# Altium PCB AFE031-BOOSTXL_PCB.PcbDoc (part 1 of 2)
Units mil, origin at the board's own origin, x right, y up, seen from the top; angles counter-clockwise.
Board outline 2300 x 2000 mil, 4 copper layers (Top Layer, POWER, GND, Bottom Layer), stack 61.6 mil thick; 92 components, 52 nets, 268 pads, 81 vias.
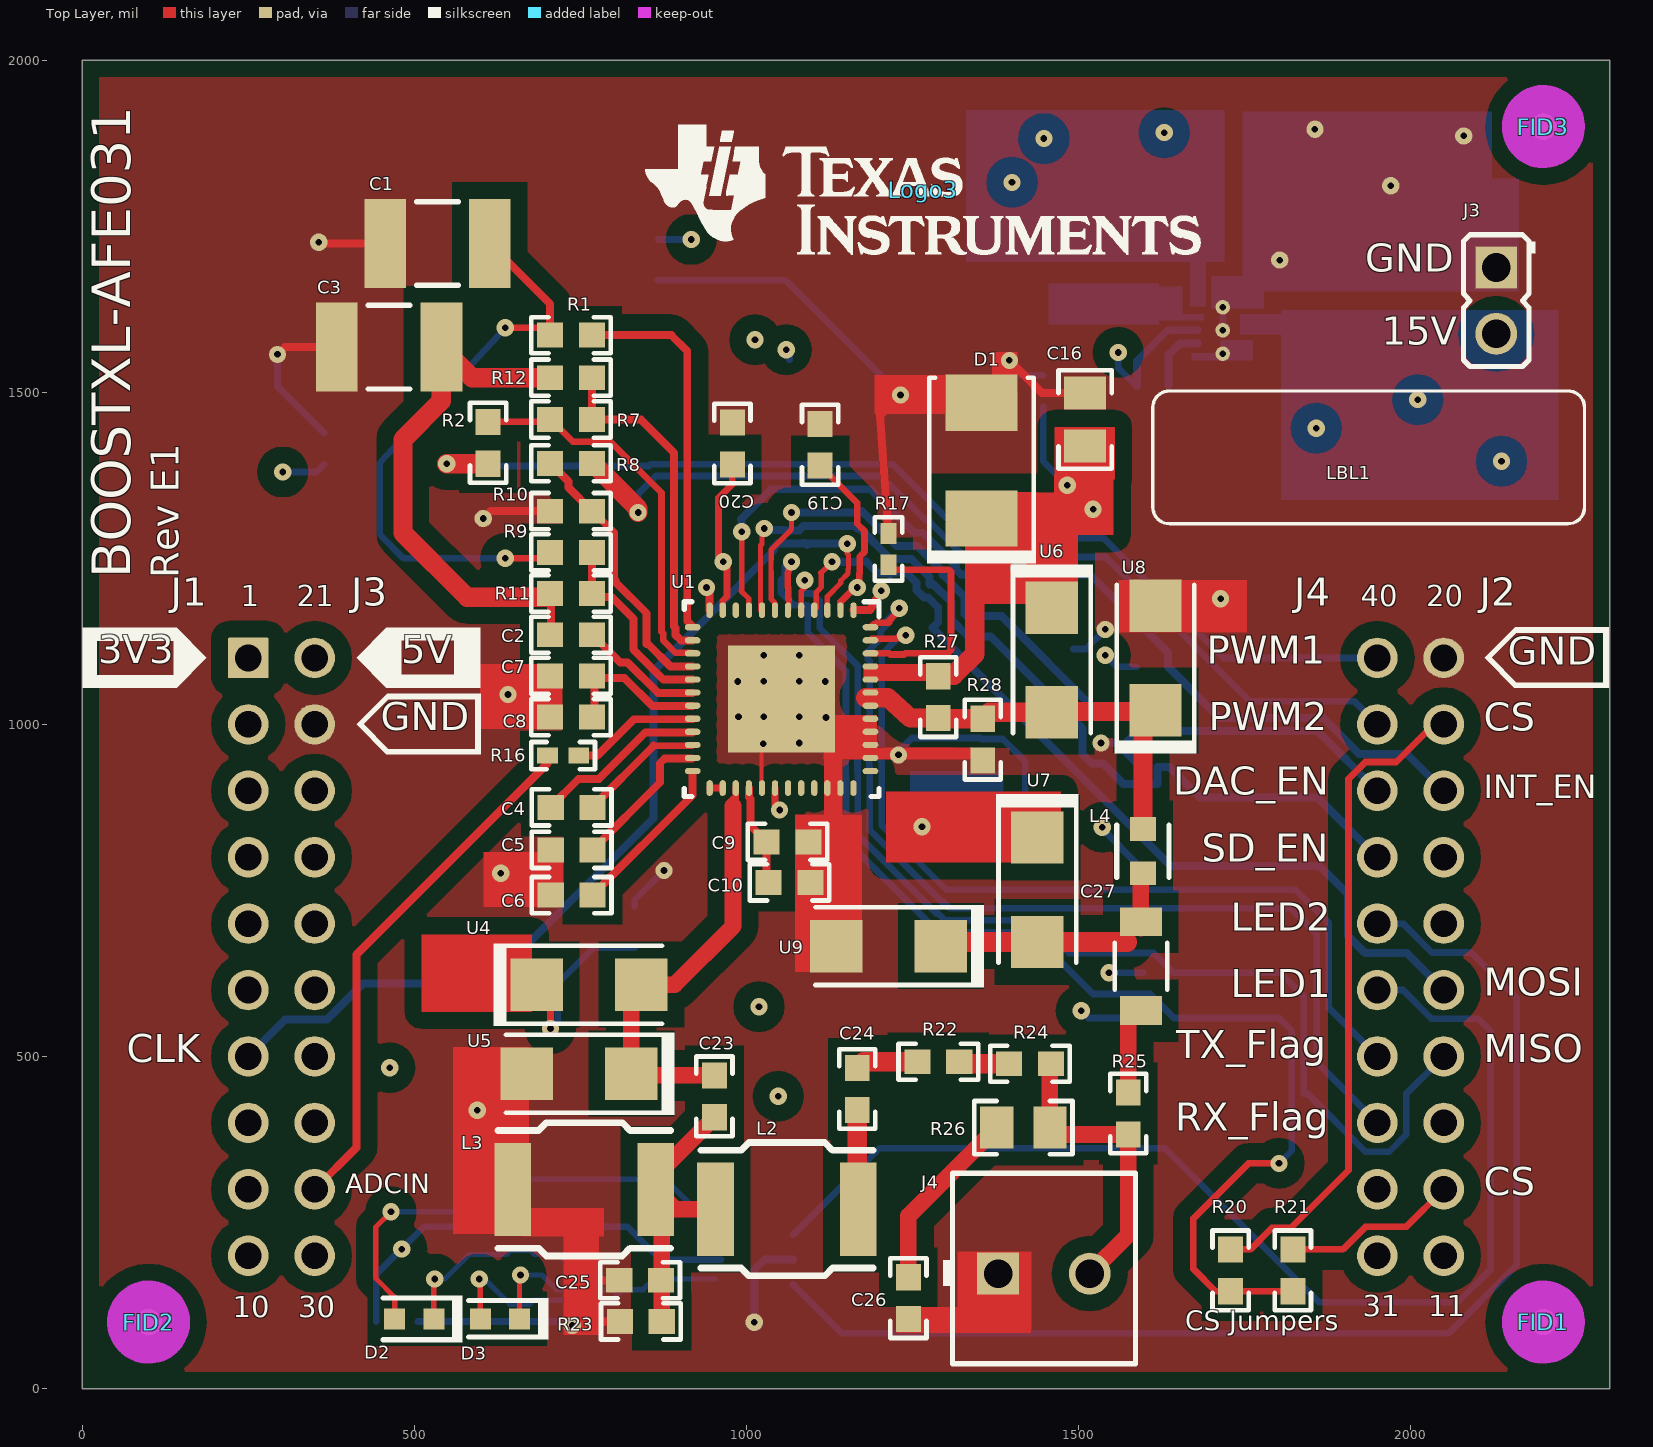
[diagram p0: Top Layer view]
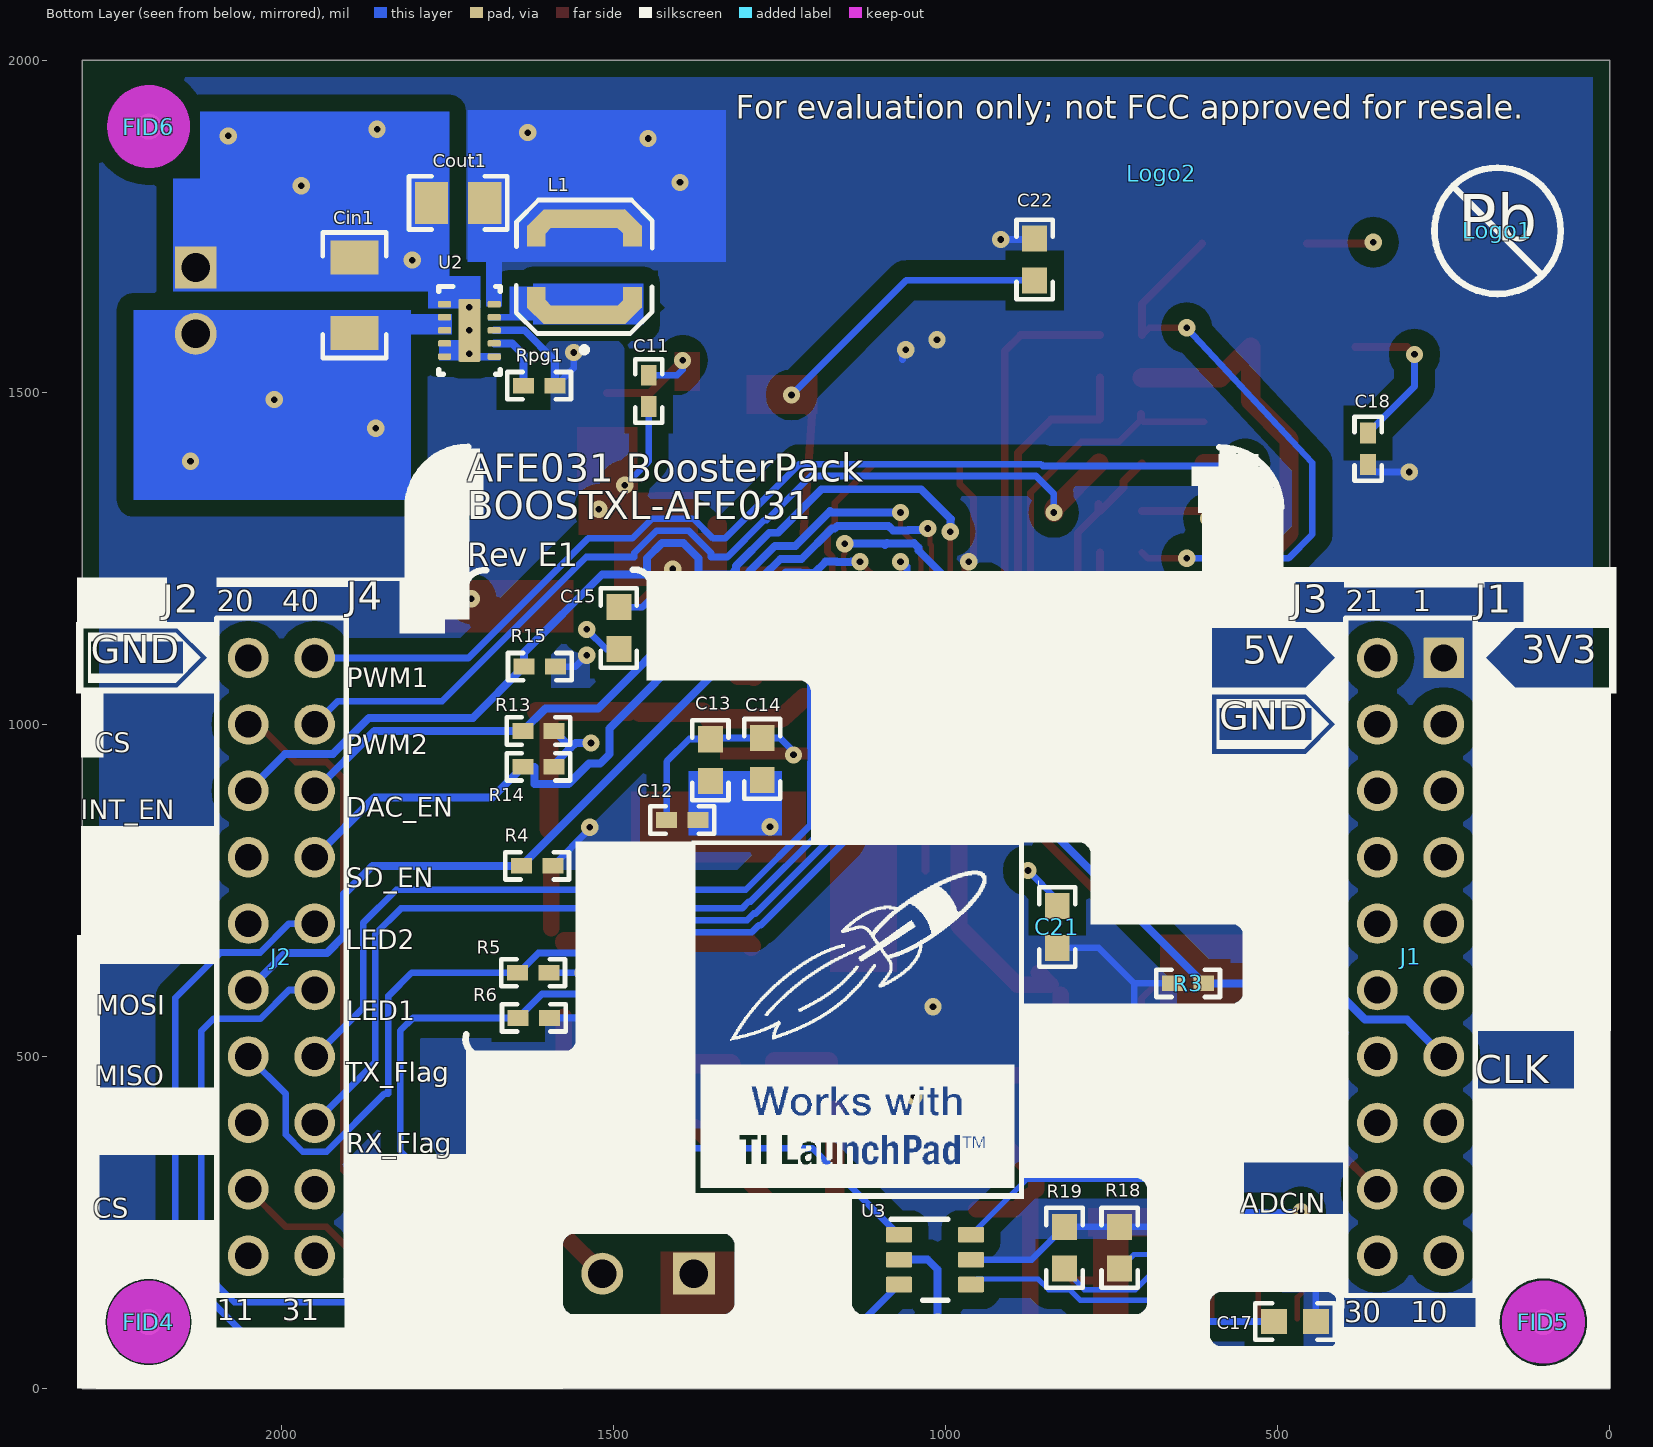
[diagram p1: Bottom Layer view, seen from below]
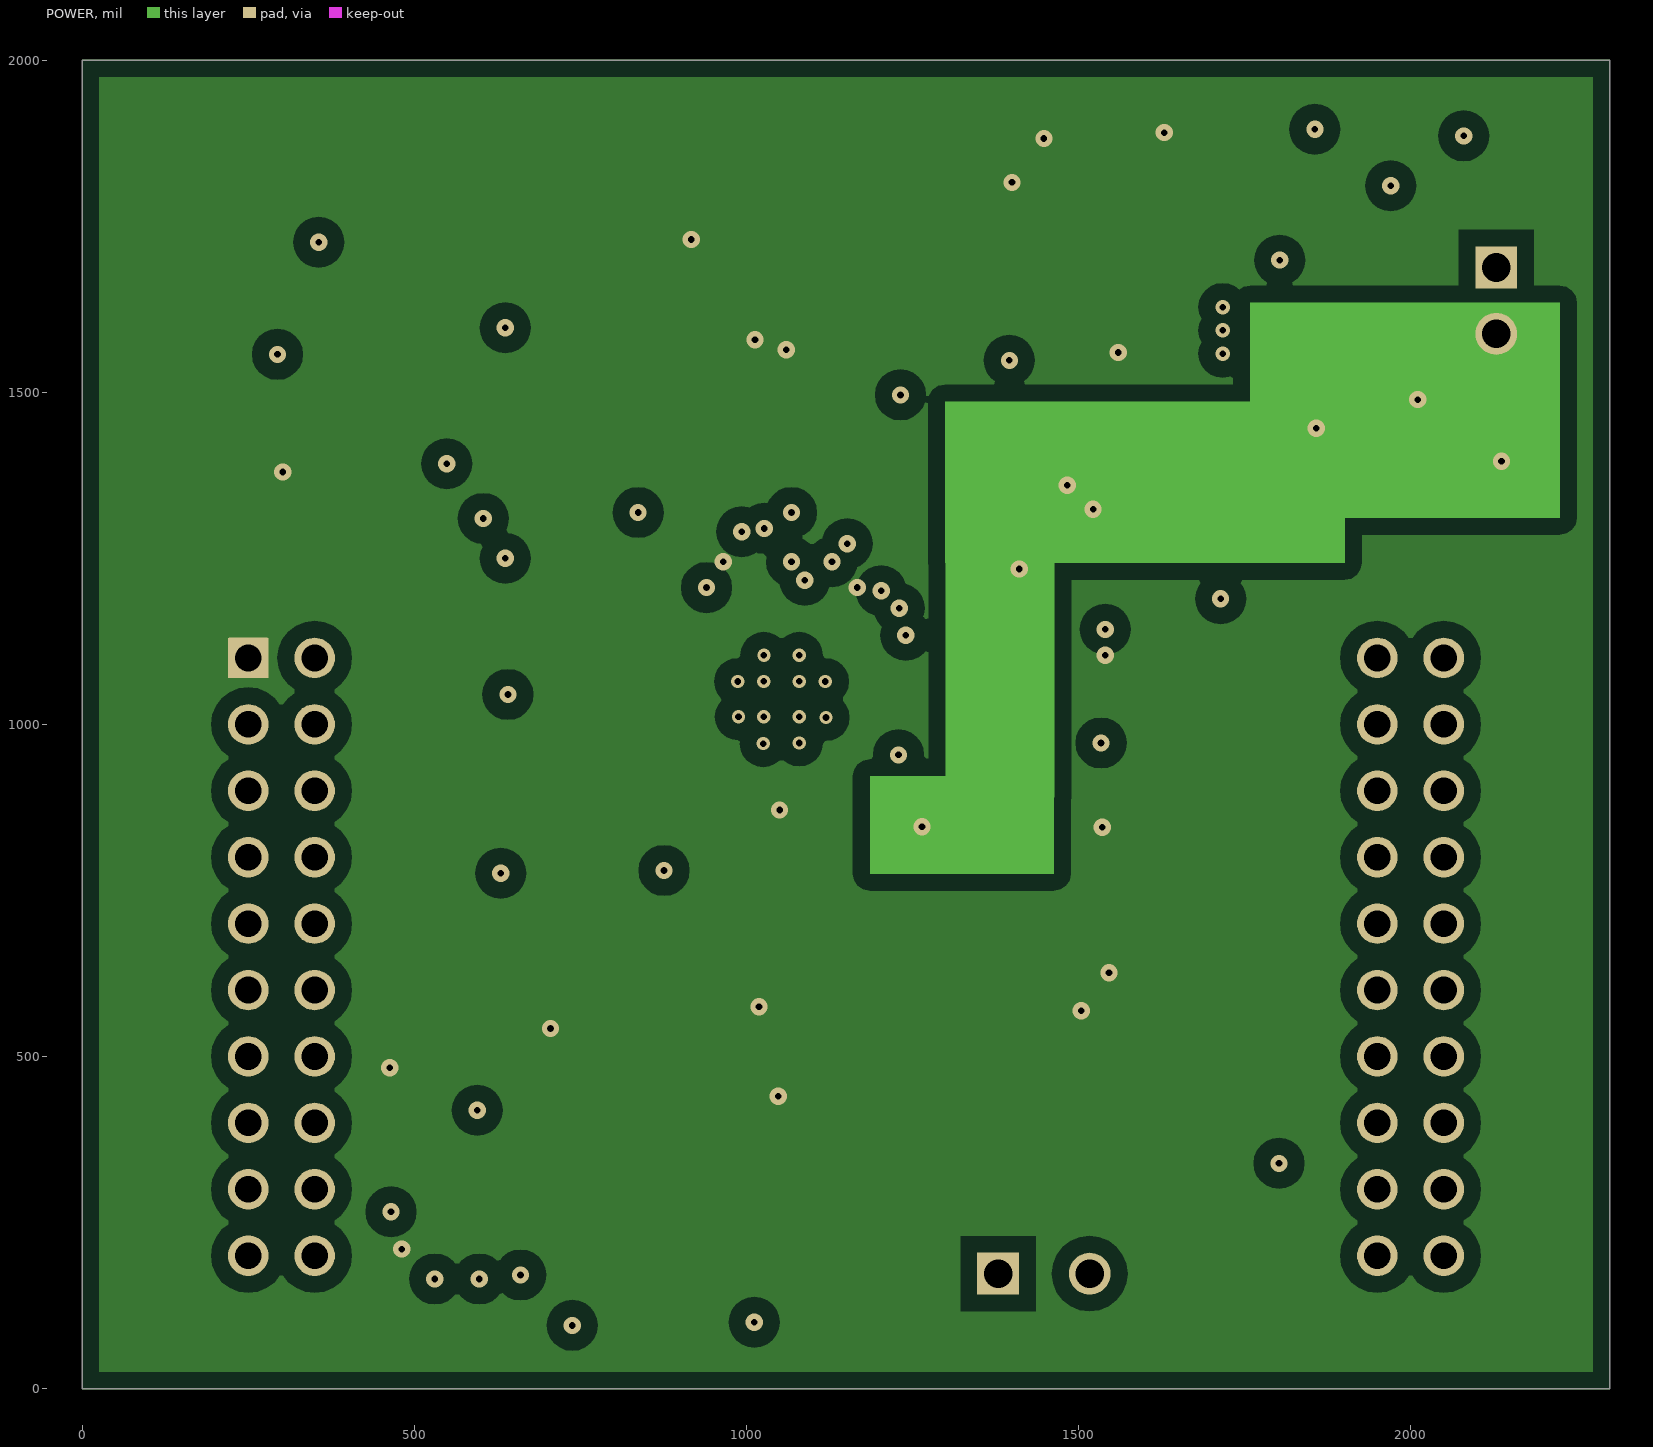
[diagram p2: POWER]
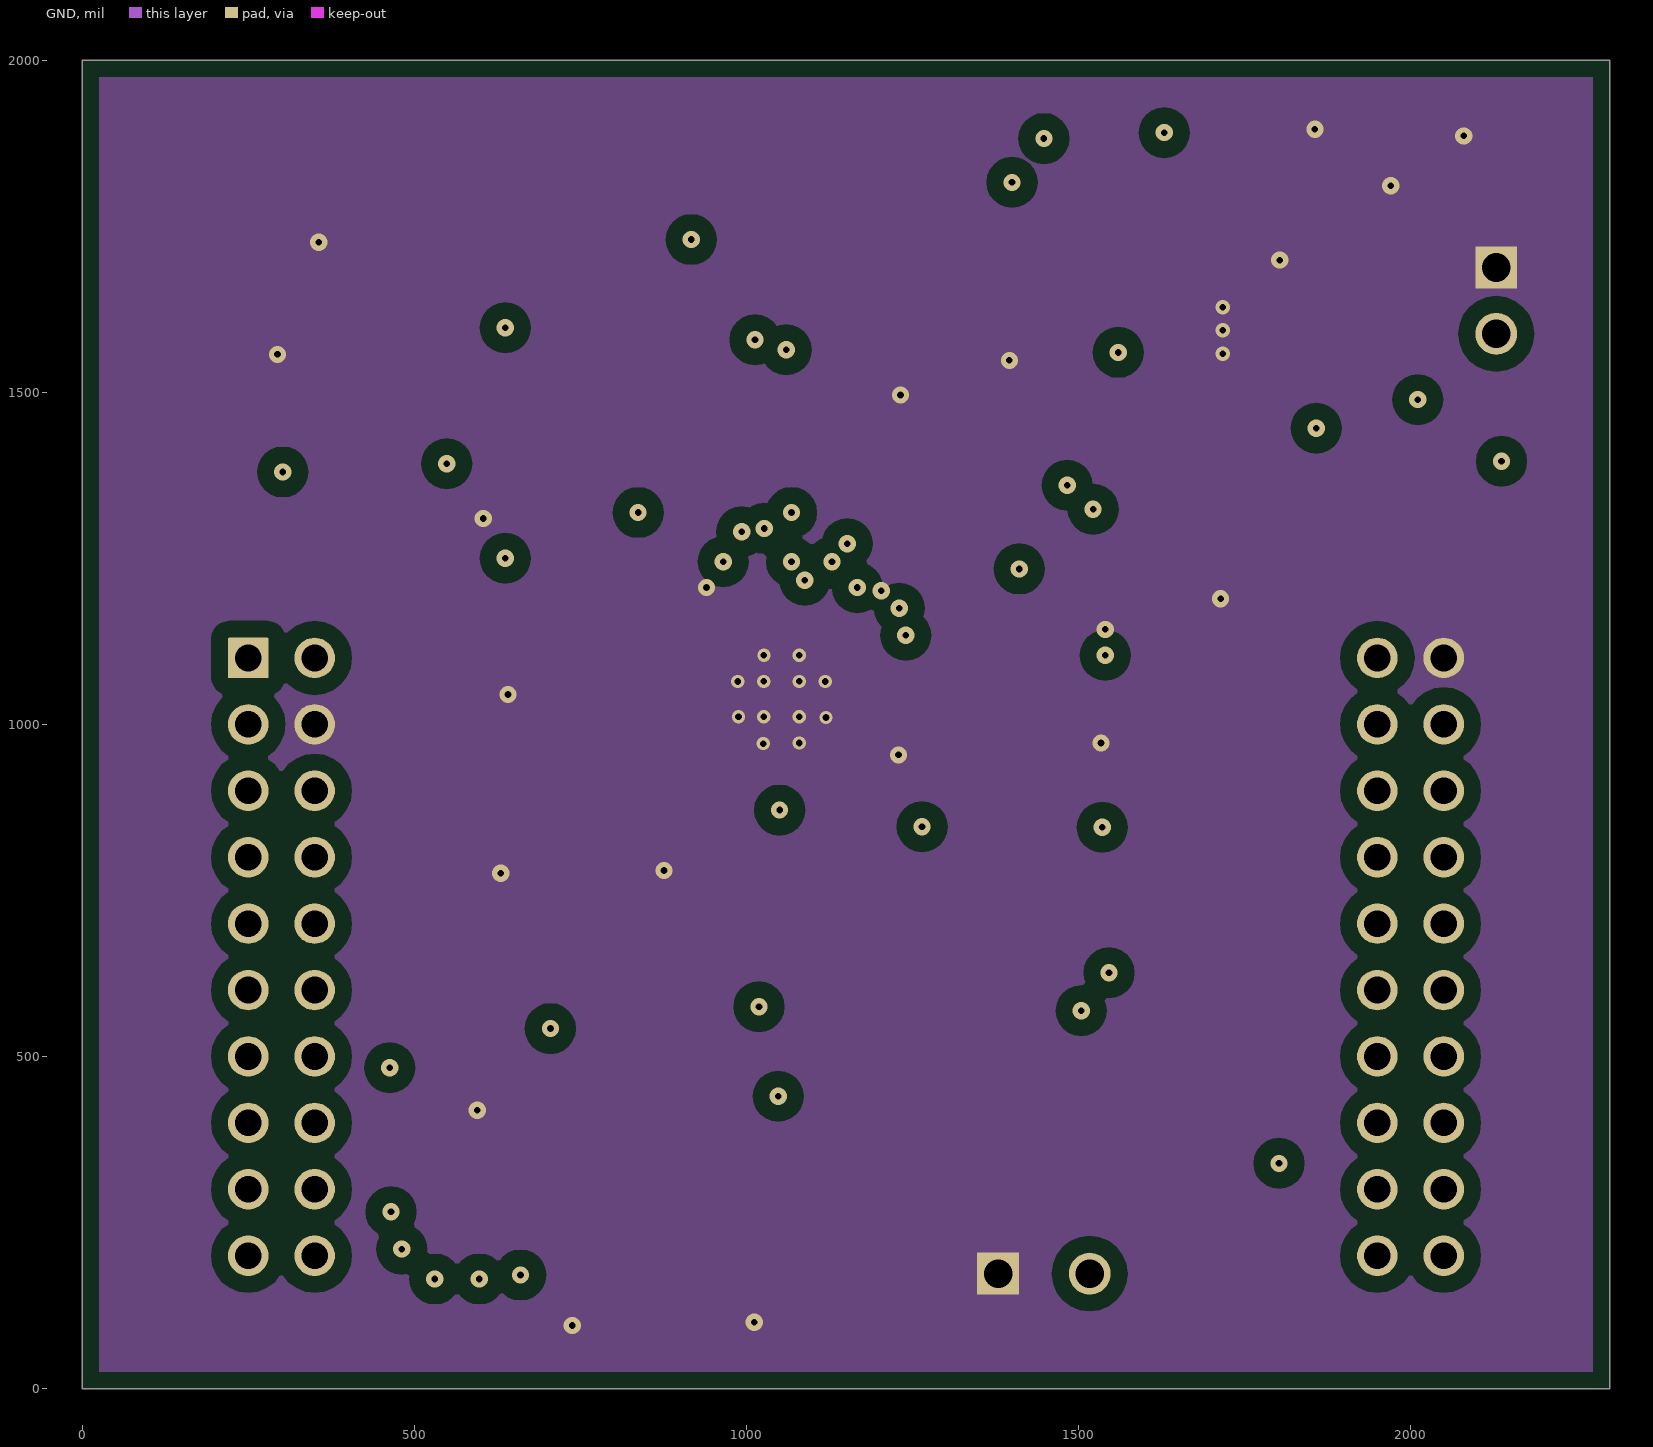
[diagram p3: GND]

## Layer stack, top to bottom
Top Solder: solder mask 0.4, Solder Resist, Dk 3.5
Top Layer: signal copper 1.4
Dielectric1: prepreg 8, FR-4, Dk 4.2
POWER: signal copper 1.4
Dielectric 2: core 40, FR-4, Dk 4.2
GND: signal copper 1.4
Dielectric 3: prepreg 8, FR-4, Dk 4.2
Bottom Layer: signal copper 1.4
Bottom Solder: solder mask 0.4, Solder Resist, Dk 3.5

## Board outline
0,0 2300,0 2300,2000 0,2000

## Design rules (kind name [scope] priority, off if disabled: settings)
AcuteAngle [All] p1: minimum=4.50000000000000E+0001 checktracksonly=FALSE
AssemblyTestPointUsage [All] p1: valid=2
BoardOutlineClearance BoardOutlineClearance_MountingHoles [OnCopper and InComponentClass('Mounting Holes')] p1: gap=40 ignorepadtopadclearanceinfootprint=FALSE
BoardOutlineClearance BoardOutlineClearance_Poly [OnCopper and IsPoly] p2: gap=25 ignorepadtopadclearanceinfootprint=FALSE
BoardOutlineClearance [OnCopper and Not InComponentClass('Logo') and not InComponentClass('FiducialMark') and not InRegion(1000,500,4000,800) and not InPoly] p3: gap=75 ignorepadtopadclearanceinfootprint=FALSE
Clearance Clearance_Keepouts [((IsTrack Or IsArc) And Not InPoly) And IsFree and IsKeepOut vs ((IsTrack Or IsArc) And Not InPoly) And IsFree and IsKeepOut] p1: gap=0 ignorepadtopadclearanceinfootprint=FALSE
Clearance Clearance_Poly [InPolygon] p2: gap=25 ignorepadtopadclearanceinfootprint=FALSE except(0: Arc-Hole Track-Hole SMDPad-Hole THPad-Hole Via-Hole Fill-Hole Poly-Hole Region-Hole Text-Hole)
Clearance [All] p3: gap=7.87 ignorepadtopadclearanceinfootprint=FALSE except(0: Arc-Hole Track-Hole SMDPad-Hole THPad-Hole Via-Hole Fill-Hole Poly-Hole Region-Hole Text-Hole)
ComponentClearance ComponentClearance_MountingHoles_FiducialMarks [InComponentClass('Mounting Holes') vs InComponentClass('FiducialMark')] p1: gap=50 collisioncheckmode=3 verticalgap=10 showdistances=FALSE
ComponentClearance ComponentClearance_Shunt [InComponentClass('Header') vs InComponentClass('Shunt')] p2: gap=0 collisioncheckmode=3 verticalgap=0 showdistances=FALSE
ComponentClearance ComponentClearance_Logo [InComponentClass('Logo')] p3: gap=50 collisioncheckmode=3 verticalgap=10 showdistances=FALSE
ComponentClearance ComponentClearance_ScrewToNut [(HasFootprint('NY PMS 440 0025 PH')) vs (HasFootprint('Keystone_1902C'))] p4: gap=5 collisioncheckmode=3 verticalgap=10 showdistances=FALSE
ComponentClearance ComponentClearance_MountingHoles [InComponentClass('Mounting Holes')] p5: gap=250 collisioncheckmode=3 verticalgap=100000 showdistances=FALSE
ComponentClearance ComponentClearance_SmallPassives [HasFootprint('0201*') or HasFootprint('0402*') or HasFootprint('0508') or HasFootprint('0603*') or HasFootprint('0612') or HasFootprint('0805*') or HasFootprint('0815*') or HasFootprint('0830*') or HasFootprint('1206*') or HasFootprint('1210*') or HasFootprint('1808*') or HasFootprint('1812*') or HasFootprint('1825*') or HasFootprint('2010*') or HasFootprint('2220*') or HasFootprint('2225*') or HasFootprint('2512*') or HasFootprint('2728*') or HasFootprint('3518*') vs HasFootprint('0201*') or HasFootprint('0402*') or HasFootprint('0508') or HasFootprint('0603*') or HasFootprint('0612') or HasFootprint('0805*') or HasFootprint('0815*') or HasFootprint('0830*') or HasFootprint('1206*') or HasFootprint('1210*') or HasFootprint('1808*') or HasFootprint('1812*') or HasFootprint('1825*') or HasFootprint('2010*') or HasFootprint('2220*') or HasFootprint('2225*') or HasFootprint('2512*') or HasFootprint('2728*') or HasFootprint('3518*')] p6: gap=14.96 collisioncheckmode=3 verticalgap=10 showdistances=FALSE
ComponentClearance ComponentClearance_THtoSMT [IsThruComponent vs IsSMTComponent] p7: gap=30 collisioncheckmode=3 verticalgap=30 showdistances=FALSE
ComponentClearance ComponentClearance_THtoTH [IsThruComponent vs IsThruComponent] p8: gap=30 collisioncheckmode=3 verticalgap=30 showdistances=FALSE
ComponentClearance [All] p9: gap=30 collisioncheckmode=3 verticalgap=10 showdistances=FALSE
DiffPairsRouting [All] p1: maxlimit=100 minlimit=10 mostfreqgap=10 toplayer_minwidth=15 toplayer_maxwidth=15 toplayer_prefwidth=15 midlayer1_minwidth=15 midlayer1_maxwidth=15 midlayer1_prefwidth=15 midlayer2_minwidth=15 midlayer2_maxwidth=15 midlayer2_prefwidth=15 bottomlayer_minwidth=15 bottomlayer_maxwidth=15 bottomlayer_prefwidth=15 maxuncoupledlength=1000
FabricationTestPointUsage TestPointUsage [All] p1: valid=2 allowmultiple=FALSE
FabricationTestpoint Testpoint [All] p1: side=3 testpointundercomponent=TRUE minsize=40 maxsize=100 preferedsize=60 minholesize=0 maxholesize=40 preferedholesize=32 testpointgrid=1 allowsidetop=TRUE allowsidebottom=TRUE usegrid=TRUE gridtolerance=0.01
FanoutControl Fanout_LCC [IsLCC] p1: bgadir=Out bgaviamode=Centered fanoutstyle=Auto fanoutdirection=Alternating viagrid=1 // Fanout_LCC (Default Rule)
FanoutControl Fanout_BGA [IsBGA] p2: bgadir=Out bgaviamode=Centered fanoutstyle=Auto fanoutdirection=Alternating viagrid=1 // Fanout_BGA (Default Rule)
FanoutControl Fanout_Default [All] p4: bgadir=Out bgaviamode=Centered fanoutstyle=Auto fanoutdirection=Alternating viagrid=1 // Fanout_Default (Default Rule)
FanoutControl Fanout_Small [(CompPinCount < 5)] p5: bgadir=Out bgaviamode=Centered fanoutstyle=Auto fanoutdirection=OutThenIn viagrid=1 // Fanout_Small (Default Rule)
HoleSize [All] p1: absolutevalues=TRUE maxlimit=251 minlimit=7.87 maxpercent=80.000 minpercent=20.000
MinimumAnnularRing MinimumAnnularRing_ThermalPadVias [IsVia and InAnyComponent] p1: minimumring=5
MinimumAnnularRing [All] p2: minimumring=8
MinimumSolderMaskSliver MinimumSolderMaskSliver_Logo [InComponentClass('Logo') vs InComponentClass('Logo')] p1: minsoldermaskwidth=0.7
MinimumSolderMaskSliver [All] p2: minsoldermaskwidth=3.94
PlaneConnect [All] p1: planeconnectstyle=Direct reliefexpansion=10 reliefentries=4 reliefconductorwidth=10 reliefairgap=10
PolygonConnect [All] p1: connectstyle=Direct reliefconductorwidth=10 reliefentries=4 polygonreliefangle="90 Angle" airgapwidth=10
RoutingVias ThermalPadVias [IsVia and InAnyComponent] p1: holewidth=7.87 width=19.68 viastyle="Through Hole" minholewidth=7.87 minwidth=19.68 maxholewidth=12.99 maxwidth=23.62
RoutingVias [All] p2: holewidth=16 width=34 viastyle="Through Hole" minholewidth=7.87 minwidth=20 maxholewidth=40 maxwidth=65
SilkToBoardRegionClearance [Not ((IsComment or IsDesignator) And (Hide <> 'False')) and not InRegion(1000,500,4000,800)] p1:
SilkToSilkClearance SilkToSilkClearance_Pb-FreeLogo [(HasFootprint('Pb-Free_Overlay_Medium') OR HasFootprint('Pb-Free_Overlay_Small')) vs (HasFootprint('Pb-Free_Overlay_Medium') OR HasFootprint('Pb-Free_Overlay_Small'))] p1: silktosilkclearance=0
SilkToSilkClearance [All] p2: silktosilkclearance=0
SilkToSolderMaskClearance SilkToComponentPadClearance [IsPad and InAnycomponent] p1: minsilkscreentomaskgap=3 clearancetoexposedcopper=TRUE
SilkToSolderMaskClearance "Silk to Solder Mask Opening" [All] p2: minsilkscreentomaskgap=1 clearancetoexposedcopper=FALSE
SolderMaskExpansion [All] p1: expansion=1.97
Width [All] p1: maxlimit=100 minlimit=6 preferedwidth=10 checkconnectedcopper=TRUE
15 further rules are at their usual default settings.

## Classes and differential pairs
component class AFE031-BOOSTXL_PassiveFilters: C23 C24 C25 C26 C27 L2 L3 L4 R22 R23 R24 R25 R26 R27 R28 U4 U5 U6 U7 U8 U9
component class AFE031-BOOSTXL_EVM_Hardware: !PCB1 FID1 FID2 FID3 FID4 FID5 FID6 LBL1 Logo1 Logo2 Logo3 ZZ1 ZZ2 ZZ3 ZZ4
component class AFE031-BOOSTXL_Connectors: J1 J2 J3 J4 R20 R21
component class AFE031-BOOSTXL_AFE: C1 C2 C3 C4 C5 C6 C7 C8 C9 C10 C11 C12 C13 C14 C15 C16 C17 C18 C19 C20 C21 C22 Cin1 Cout1 D1 D2 D3 L1 R1 R2 R3 R4 R5 R6 R7 R8 R9 R10 R11 R12 R13 R14 R15 R16 R17 R18 R19 Rpg1 Text U1 U2 U3
component class Header: J3
component class FiducialMark: FID1 FID2 FID3 FID4 FID5 FID6
component class AssemblyNote: ZZ1 ZZ2 ZZ3 ZZ4
component class Label: LBL1
component class Logo: Logo3

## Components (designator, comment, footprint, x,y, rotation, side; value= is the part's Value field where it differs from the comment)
C1 "GR443QR73D102KW01L" 1812 535,1724 r180 top value=1000pF
C2 "GRM1885C1H332JA01D" 0603 736,1135 r0 top value=3300pF
C3 "GR443QR73D102KW01L" 1812 462,1568 r180 top value=1000pF
C4 "GRM188R71C103KA01D" 0603 737,875 r180 top value=0.01uF
C5 "GRM1885C1H561JA01D" 0603 737,811 r180 top value=560pF
C6 "06035A271JAT2A" 0603 737,743 r180 top value=270pF
C7 "UMK107AB7105KA-T" 0603 736,1073 r180 top value=1uF
C8 "GRM188R71C102KA01D" 0603 736,1011 r180 top value=1000pF
C9 "UMK107AB7105KA-T" 0603 1062,823 r0 top value=1uF
C10 "GRM188R71C102KA01D" 0603 1065,762 r0 top value=1000pF
C11 "160R07X104KV4T" 0402_065 1447,1502 r90 bottom value=0.1uF
C12 "160R07X104KV4T" 0402_065 1396.5,856 r0 bottom value=0.1uF
C13 "GRM188R71C103KA01D" 0603 1354,946 r90 bottom value=0.01uF
C14 "GRM188R71C103KA01D" 0603 1276,948 r90 bottom value=0.01uF
C15 "GRT188R61E106ME13D" 0603 1492,1145 r90 bottom value=10uF
C16 "JMK212BJ476MG-T" 0805_HV 1510,1459 r90 top value=47uF
C17 "0603YC104JAT2A" 0603 474,101 r0 bottom value=0.1uF
C18 "160R07X104KV4T" 0402_065 364,1415 r90 bottom value=0.1uF
C19 "GRM188R71C103KA01D" 0603 1111,1421 r90 top value=0.01uF
C20 "GRM188R71C103KA01D" 0603 979,1423 r90 top value=0.01uF
C21 "GRM188R71C103KA01D" 0603 832,695 r90 bottom value=0.01uF
C22 "GRT188R61E106ME13D" 0603 866,1700 r90 bottom value=10uF
C23 "GCM188R71H103KA37D" 0603 952,440 r90 top value=0.01uF
C24 "06035C333JAT2A" 0603 1167,451 r270 top value=0.033uF
C25 "GRM188R71H223KA01D" 0603 840,163 r180 top value=0.022uF
C26 "06035A102KAT2A" 0603 1244,136 r270 top value=1000pF
C27 "GRT31CR61H106KE01L" 1206_180 1594,636 r90 top value=10uF
Cin1 "GRM31MR71E225KA93L" 1206 1890,1646 r90 bottom value=2.2uF
Cout1 "GRM21BR60J226ME39L" 0805_HV 1734,1785.2 r0 bottom value=22uF
D1 "1SMB5931BT3G" SMB 1354,1397 r90 top value=18V
D2 "150060BS75000" LTST-C193_Blue 500,105 r0 top value=Blue
D3 "150060RS75000" LTST-C191_Red 629,105 r0 top value=Red
FID1 "Fiducial" Fiducial10-30 2200,100 r0 top
FID2 "Fiducial" Fiducial10-30 100,100 r0 top
FID3 "Fiducial" Fiducial10-30 2200,1900 r0 top
FID4 "Fiducial" Fiducial10-30 2200,100 r180 bottom
FID5 "Fiducial" Fiducial10-30 100,100 r180 bottom
FID6 "Fiducial" Fiducial10-30 2200,1900 r180 bottom
J1 "SSQ-110-03-T-D" BoosterPack_40pin_J1J3 300,650 r180 bottom locked
J2 "SSQ-110-03-T-D" BoosterPack_40pin_J2J4 2000,650 r180 bottom locked
J3 "961102-6404-AR" 3M_961102-6404-AR 2129,1638 r270 top
J4 "39357-0002" Molex_39357-0002 1448,173 r0 top
L1 "LPS4018-103MRB" LPS4018 1544,1689 r90 bottom value=10uH
L2 "DO1608C-334MLB" DO1608C 1061,270 r0 top value=330uH
L3 "DO1608C-474MLB" DO1608C 756,300 r180 top value=470uH
L4 "LQH2MCN1R0M52" LQH2MC_52 1597,809 r270 top value=1uH
LBL1 "Size: 0.65\" x 0.20 \"" Label_650x200 1937,1402 r0 top
Logo1 "Pb-Free Symbol" Pb-Free_Overlay_Medium 169,1743 r180 bottom
Logo2 "FCC disclaimer" FCC_disclaimer 674.8,1830 r180 bottom
Logo3 "Texas Instruments" TI_Stacked_Overlay_Small 1266,1805 r0 top
R1 "CRCW06030000Z0EA" 0603 736,1586 r180 top value=0
R2 "CRCW060343K0JNEA" 0603 611,1424 r270 top value=43k
R3 "CRCW040210K0FKED" 0402 635,610 r0 bottom value=10.0k
R4 "CRCW040210K0FKED" 0402 1615,787 r180 bottom value=10.0k
R5 "CRCW040210K0FKED" 0402 1621,626 r180 bottom value=10.0k
R6 "CRCW040210K0FKED" 0402 1620,558 r180 bottom value=10.0k
R7 "CRCW06030000Z0EA" 0603 736,1459 r0 top value=0
R8 "CRCW060343K0JNEA" 0603 736,1393 r0 top value=43k
R9 "RC0603JR-07510RL" 0603 736,1259 r180 top value=510
R10 "CRCW06030000Z0EA" 0603 736,1321 r0 top value=0
R11 "CRCW06030000Z0EA" 0603 736,1197 r0 top value=0
R12 "RC0603JR-07510RL" 0603 736,1522 r0 top value=510
R13 "CRCW040210K0FKED" 0402 1613,990 r0 bottom value=10.0k
R14 "CRCW040210K0FKED" 0402 1613,936 r0 bottom value=10.0k
R15 "CRCW040233K0JNED" 0402 1611,1087 r0 bottom value=33k
R16 "CRCW0402330RJNED" 0402 724,953 r180 top value=330
R17 "CRCW040210K0FKED" 0402 1214,1264 r270 top value=10.0k
R18 "CRCW0603680RJNEA" 0603 738,212 r90 bottom value=680
R19 "CRCW0603680RJNEA" 0603 821,212 r90 bottom value=680
R20 "CRCW06030000Z0EA" 0603 1729,178 r90 top value=0
R21 "CRCW06030000Z0EA" 0603 1823,178 r90 top value=0
R22 "CRCW0603150RFKEA" 0603 1289,492 r180 top value=150
R23 "CRCW0603150RFKEA" 0603 841,101 r0 top value=150
R24 "CRCW06030000Z0EA" 0603 1427,489 r180 top value=0
R25 "CRCW06030000Z0EA" 0603 1575,414 r90 top value=0
R26 "ERJ-6GEYJ4R7V" 0805_HV 1417,393 r0 top value=4.7
R27 "RC0603FR-07100KL" 0603 1289,1041 r90 top value=100k
R28 "RC0603FR-07100KL" 0603 1356,977 r90 top value=100k
Rpg1 "ERJ-2RKF1000X" 0402 1612,1510 r0 bottom value=100
U1 "AFE031AIRGZT" "RGZ0048B - Thicker Vias" 1053,1038 r270 top
U2 "TPS62177DQCR" DQC0010A-Edited 1717,1593.2 r180 bottom
U3 "SN74LVC2G07DBVR" DBV0006A_N 1016,194 r180 bottom
U4 "B350A-13-F" SMA 763,608 r0 top value=50V
U5 "B350A-13-F" SMA 748,474 r180 top value=50V
U6 "B350A-13-F" SMA 1460,1097 r270 top value=50V
U7 "B350A-13-F" SMA 1438,751 r270 top value=50V
U8 "B350A-13-F" SMA 1616,1100 r90 top value=50V
U9 "B350A-13-F" SMA 1214,666 r180 top value=50V
ZZ1 "This Assembly Note is for PCB labels only" AssemblyNoteLabel 185,3938 r0 top
ZZ2 "This Assembly Note will show in the PcbDoc and associated outputs" AssemblyNote 185,3829.11 r0 top
ZZ3 "This Assembly Note will show in the PcbDoc and associated outputs" AssemblyNote 185,3740.56 r0 top
ZZ4 "This Assembly Note will show in the PcbDoc and associated outputs" AssemblyNote 185,3652 r0 top

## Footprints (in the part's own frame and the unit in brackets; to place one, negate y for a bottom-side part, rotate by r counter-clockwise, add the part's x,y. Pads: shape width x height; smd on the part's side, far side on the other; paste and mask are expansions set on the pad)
3M_961102-6404-AR [mm] "Header, 2.54mm, 2x1, TH"
  rect 1.6x1.6 hole 1.1: 1(-1.27,0)
  round 1.6 hole 1.1: 2(1.27,0)
  silkscreen extent -2.52,-1.25 2.52,1.5, body extent -2.52,-1.25 2.52,1.25, height 8.5
0402 [mm] "0402 from SM-752 data"
  rect 0.8x0.6 smd: 1(-0.6,0) 2(0.6,0)
  silkscreen extent -1.22,-0.52 1.22,0.52, body extent -0.55,-0.3 0.55,0.3, height 0.6
0402_065 [mm] "0402"
  rect 0.8x0.6 smd: 1(-0.6,0) 2(0.6,0)
  silkscreen extent -1.22,-0.52 1.22,0.52, body extent -0.55,-0.3 0.55,0.3, height 0.65
0603 [mm] "0603 from SM-752 data"
  rect 1x0.95 smd: 1(-0.8,0) 2(0.8,0)
  silkscreen extent -1.52,-0.69 1.52,0.69, body extent -0.87,-0.47 0.87,0.47, height 1
0805_HV [mil] "0805 with 30mil clearance between pads"
  rect 50x63 smd: 1(-40,0) 2(40,0)
  silkscreen extent -74,-40 74,40, body extent -43,-29 43,29, height 57
1206 [mm] "1206 from SM-752 data"
  rect 1.3x1.85 smd: 1(-1.45,0) 2(1.45,0)
  silkscreen extent -2.4,-1.21 2.4,1.21, body extent -1.7,-0.9 1.7,0.9, height 1.35
1206_180 [mm] "1206_180"
  rect 1.1x1.6 smd: 1(-1.7,0) 2(1.7,0)
  silkscreen extent -0.9,-1 0.9,1, body extent -1.75,-0.95 1.75,0.95, height 1.8
1812 [mm]
  rect 1.6x3.4 smd: 1(-2,0) 2(2,0)
  silkscreen extent -0.8,-1.6 0.8,1.6, body extent -2.4,-1.7 2.4,1.7, height 1.35
AssemblyNote [mil] "Assembly Note"
AssemblyNoteLabel [mil] "Assembly Note for PCB Labels"
BoosterPack_40pin_J1J3 [mm] "Receptacle, 2.54mm, 10x2, TH"
  rrect6% 1.55x1.55 hole 1.02: 1(1.27,11.43)
  round 1.55 hole 1.02: 2(1.27,8.89) 3(1.27,6.35) 4(1.27,3.81) 5(1.27,1.27) 6(1.27,-1.27) 7(1.27,-3.81) 8(1.27,-6.35) 9(1.27,-8.89) 10(1.27,-11.43) 21(-1.27,11.43) 22(-1.27,8.89) 23(-1.27,6.35) 24(-1.27,3.81) 25(-1.27,1.27) 26(-1.27,-1.27) 27(-1.27,-3.81) 28(-1.27,-6.35) 29(-1.27,-8.89) 30(-1.27,-11.43)
  silkscreen extent -2.48,-12.95 2.48,12.95, body extent -2.48,-12.95 2.48,12.95, height 8.51
BoosterPack_40pin_J2J4 [mm] "Receptacle, 2.54mm, 10x2, TH"
  round 1.55 hole 1.02: 11(-1.27,-11.43) 12(-1.27,-8.89) 13(-1.27,-6.35) 14(-1.27,-3.81) 15(-1.27,-1.27) 16(-1.27,1.27) 17(-1.27,3.81) 18(-1.27,6.35) 19(-1.27,8.89) 20(-1.27,11.43) 31(1.27,-11.43) 32(1.27,-8.89) 33(1.27,-6.35) 34(1.27,-3.81) 35(1.27,-1.27) 36(1.27,1.27) 37(1.27,3.81) 38(1.27,6.35) 39(1.27,8.89) 40(1.27,11.43)
  silkscreen extent -2.48,-12.95 2.48,12.95, body extent -2.48,-12.95 2.48,12.95, height 8.51
DBV0006A_N [mm] "SOT23, 6-Leads, Body 2.9x1.6mm, Pitch 0.95mm, Lead Span 2.8mm, IPC Medium Density"
  rrect17% 1x0.6 smd: 1(-1.375,0.95) 2(-1.375,0) 3(-1.375,-0.95) 4(1.375,-0.95) 5(1.375,0) 6(1.375,0.95)
  silkscreen extent -1.68,-1.55 0.5,1.55, body extent -1.42,-1.46 1.42,1.46, height 1.12
DO1608C [mm] "DO1608C"
  rect 1.4x3.56 smd: 1(-2.73,0) 2(2.73,0)
  silkscreen extent -3.3,-2.55 3.3,2.55, body extent -3.27,-2.22 3.33,2.23, height 2.92
DQC0010A-Edited [mm] "SON, 10-Leads, Body 2.1x3.1mm, Pitch 0.5mm, Thermal Pad 2.4x0.8mm"
  rrect40% 0.5x0.25 smd: 1(-0.95,1) 2(-0.95,0.5) 3(-0.95,0) 4(-0.95,-0.5) 5(-0.95,-1) 6(0.95,-1) 7(0.95,-0.5) 8(0.95,0) 9(0.95,0.5) 10(0.95,1)
  rrect12% 0.8x1.08 on Bottom Paste: 11(0,-0.64) 11(0,0.64)
  rrect12% 0.84x2.4 smd paste-0.42: 11(0,0)
  silkscreen extent -1.17,-1.68 1.17,1.68, body extent -1,-1.5 1,1.5, height 0.77
FCC_disclaimer [mil]
Fiducial10-30 [mm]
  round 1 smd mask+1: 1(0,0)
  Top Layer keep-out circle w1.678: c0,0 r0.75
Label_650x200 [mil] "Thermal Transfer Label"
  silkscreen extent -325,-100 325,100, body extent -325,-100 325,100, height 1
LPS4018 [mil]
  rect 28x123 smd: 1(-72.5,0) 2(72.5,0)
  rect 35.5x28 smd rot 135: 1(-64,-64) 2(64,64)
  rect 35.5x28 smd rot 45: 1(-64,64) 2(64.5,-63.5)
  rect 31.5x28 smd: 1(-46,-72.5) 1(-46,72.5) 2(46,-72.5) 2(46,72.5)
  silkscreen extent -129,-102 100,102, body extent -81,-81 81,81, height 71
LQH2MC_52 [mm] "MuRata"
  rect 0.9x1 smd: 1(-0.85,0) 2(0.85,0)
  silkscreen extent -1,-1 1,1, body extent -1.1,-0.9 1.1,0.9, height 0.7
LTST-C191_Red [mm] "SMD, 2-Leads, Body1.6x0.8mm"
  rect 0.8x0.8 smd: 1(-0.75,0) 2(0.75,0)
  silkscreen extent -1.2,-0.8 1.85,0.8, body extent -0.85,-0.45 0.85,0.45, height 0.66
LTST-C193_Blue [mm] "SMD, 2-Leads, Body1.6x0.8mm"
  rect 0.8x0.8 smd: 1(-0.75,0) 2(0.75,0)
  silkscreen extent -1.2,-0.9 1.85,0.9, body extent -0.85,-0.45 0.85,0.45, height 0.45
Molex_39357-0002 [mm] "Terminal Block, 3.5 mm, 2x1, TH"
  rect 1.6x1.6 hole 1.1: 1(-1.75,0)
  round 1.6 hole 1.1: 2(1.75,0)
  silkscreen extent -3.86,-3.45 3.5,3.84, body extent -3.55,-3.45 3.56,3.84, height 8.51
Pb-Free_Overlay_Medium [mil]
  silkscreen extent -95,-95 95,95
"RGZ0048B - Thicker Vias" [mm] "QFN, 48-Leads, Body 7x7mm, Pitch 0.5mm, Thermal Pad 5.15x5.15mm, TI Recommended"
  oval 0.6x0.24 smd: 1(-3.4,2.75) 2(-3.4,2.25) 3(-3.4,1.75) 4(-3.4,1.25) 5(-3.4,0.75) 6(-3.4,0.25) 7(-3.4,-0.25) 8(-3.4,-0.75) 9(-3.4,-1.25) 10(-3.4,-1.75) 11(-3.4,-2.25) 12(-3.4,-2.75) 25(3.4,-2.75) 26(3.4,-2.25) 27(3.4,-1.75) 28(3.4,-1.25) 29(3.4,-0.75) 30(3.4,-0.25) 31(3.4,0.25) 32(3.4,0.75) 33(3.4,1.25) 34(3.4,1.75) 35(3.4,2.25) 36(3.4,2.75)
  oval 0.24x0.6 smd: 13(-2.75,-3.4) 14(-2.25,-3.4) 15(-1.75,-3.4) 16(-1.25,-3.4) 17(-0.75,-3.4) 18(-0.25,-3.4) 19(0.25,-3.4) 20(0.75,-3.4) 21(1.25,-3.4) 22(1.75,-3.4) 23(2.25,-3.4) 24(2.75,-3.4) 37(2.75,3.4) 38(2.25,3.4) 39(1.75,3.4) 40(1.25,3.4) 41(0.75,3.4) 42(0.25,3.4) 43(-0.25,3.4) 44(-0.75,3.4) 45(-1.25,3.4) 46(-1.75,3.4) 47(-2.25,3.4) 48(-2.75,3.4)
  rect 4.1x4.1 smd paste-2.575: 49(0,0)
  silkscreen extent -3.72,-3.72 3.72,3.72, body extent -3.57,-3.58 3.58,3.57, height 1.01
SMA [mm] "Molded Diode, 2-Leads, Body 4.3x2.6mm, IPC Medium Density, based on OnSemi component dimensions and land pattern"
  rect 2x2 smd: 1(-2,0) 2(2,0)
  silkscreen extent -3.66,-1.57 2.79,1.57, body extent -2.6,-1.3 2.6,1.3, height 2.42
SMB [mil] "Molded Diode, 2-Leads, Body 5.4x3.6mm, IPC Medium Density, based on OnSemi component dimensions"
  rect 85x107.99 smd: 1(-87.01,0) 2(87.01,0)
  silkscreen extent -155,-82 125,82, body extent -106,-71 106,71, height 91
TI_Stacked_Overlay_Small [mil]
  silkscreen extent -418,-98 418,98

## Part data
C1 C3: "CAP, CERM, 1000 pF, 2000 V, +/- 10%, X7R, 1812", Cap_Case=1812, Manufacturer=MuRata, TempCo=X7R, Tolerance_%=10, Value1=Unknown, Value2=2000V, ValueDisplayed=1000pF
C2: "CAP, CERM, 3300 pF, 50 V, +/- 5%, C0G/NP0, 0603", Cap_Case=0603, Manufacturer=MuRata, Supplier Part Number 1=GRM1885C1H332JA01D-ND, TempCo=C0G/NP0, Tolerance_%=5, Value1=Unknown, Value2=50V, ValueDisplayed=3300pF
C4 C13 C14 C19 C20 C21: "CAP, CERM, 0.01 µF, 16 V, +/- 10%, X7R, 0603", Cap_Case=0603, Manufacturer=MuRata, Supplier Part Number 1=490-1525-1-ND, TempCo=X7R, Tolerance_%=10, Value1=Unknown, Value2=16V, ValueDisplayed=0.01µF
C5: "CAP, CERM, 560 pF, 50 V, +/- 5%, C0G/NP0, 0603", Cap_Case=0603, Manufacturer=MuRata, Supplier Part Number 1=490-1445-1-ND, TempCo=C0G/NP0, Tolerance_%=5, Value1=Unknown, Value2=50V, ValueDisplayed=560pF
C6: "CAP, CERM, 270 pF, 50 V, +/- 5%, C0G/NP0, 0603", Cap_Case=0603, Manufacturer=AVX, Supplier Part Number 1=478-1180-1-ND, TempCo=C0G/NP0, Tolerance_%=5, Value1="0.077 ohm", Value2=50V, ValueDisplayed=270pF
C7 C9: "CAP, CERM, 1 µF, 50 V, +/- 10%, X7R, 0603", Cap_Case=0603, Manufacturer="Taiyo Yuden", Supplier Part Number 1=587-3247-1-ND, TempCo=X7R, Tolerance_%=10, Value1=Unknown, Value2=50V, ValueDisplayed=1µF
C8 C10: "CAP, CERM, 1000 pF, 16 V, +/- 10%, X7R, 0603", Cap_Case=0603, Manufacturer=MuRata, Supplier Part Number 1=GRM188R71C102KA01D-ND, TempCo=X7R, Tolerance_%=10, Value1=Unknown, Value2=16V, ValueDisplayed=1000pF
C11 C12 C18: "CAP, CERM, 0.1 µF, 16 V, +/- 10%, X5R, 0402", Cap_Case=0402, Manufacturer="Johanson Technology", Supplier Part Number 1=709-1129-1-ND, TempCo=X5R, Tolerance_%=10, Value1=Unknown, Value2=16V, ValueDisplayed=0.1µF
C15 C22: "CAP, CERM, 10 µF, 25 V, +/- 20%, X5R, 0603", Cap_Case=0603, Manufacturer=MuRata, Supplier Part Number 1=490-12323-1-ND, TempCo=X5R, Tolerance_%=20, Value1=Unknown, Value2=25V, ValueDisplayed=10µF
C16: "CAP, CERM, 47 µF, 6.3 V, +/- 20%, X5R, 0805", Cap_Case=0805, Manufacturer="Taiyo Yuden", Supplier Part Number 1=587-1779-1-ND, TempCo=X5R, Tolerance_%=20, Value1=Unknown, Value2=6.3V, ValueDisplayed=47µF
C17: "CAP, CERM, 0.1 µF, 16 V, +/- 5%, X7R, 0603", Cap_Case=0603, Manufacturer=AVX, Supplier Part Number 1=478-3726-1-ND, TempCo=X7R, Tolerance_%=5, Value1="0.039 ohm", Value2=16V, ValueDisplayed=0.1µF
C23: "CAP, CERM, 0.01 µF, 50 V, +/- 10%, X7R, AEC-Q200 Grade 1, 0603", Cap_Case=0603, Manufacturer=MuRata, Supplier Part Number 1=490-4778-1-ND, TempCo=X7R, Tolerance_%=10, Value1=Unknown, Value2=50V, ValueDisplayed=0.01µF
C24: "CAP, CERM, 0.033 µF, 50 V, +/- 5%, X7R, 0603", Cap_Case=0603, Manufacturer=AVX, Supplier Part Number 1=478-3723-1-ND, TempCo=X7R, Tolerance_%=5, Value1=Unknown, Value2=50V, ValueDisplayed=0.033µF
C25: "CAP, CERM, 0.022 µF, 50 V, +/- 10%, X7R, 0603", Cap_Case=0603, Manufacturer=MuRata, Supplier Part Number 1=490-1517-1-ND, TempCo=X7R, Tolerance_%=10, Value1=Unknown, Value2=50V, ValueDisplayed=0.022µF
C26: "CAP, CERM, 1000 pF, 50 V, +/- 10%, C0G/NP0, 0603", Cap_Case=0603, Manufacturer=AVX, Supplier Part Number 1=478-3718-1-ND, TempCo=C0G/NP0, Tolerance_%=10, Value1="0.048 ohm", Value2=50V, ValueDisplayed=1000pF
C27: "CAP, CERM, 10 µF, 50 V, +/- 10%, X5R, AEC-Q200 Grade 1, 1206", Cap_Case=1206, Manufacturer=MuRata, Supplier Part Number 1=490-12456-1-ND, TempCo=X5R, Tolerance_%=10, Value1=Unknown, Value2=50V, ValueDisplayed=10µF
Cin1: "CAP, CERM, 2.2 µF, 25 V, +/- 10%, X7R, 1206", Cap_Case=1210, Manufacturer=MuRata, Supplier Part Number 1=490-3368-1-ND, TempCo=X7R, Tolerance_%=10, Value1=Unknown, Value2=25V, ValueDisplayed=2.2µF
Cout1: "CAP, CERM, 22 µF, 6.3 V, +/- 20%, X5R, 0805", Cap_Case=0805, Manufacturer=MuRata, Supplier Part Number 1=81-GRM21R60J226ME39L, TempCo=X5R, Tolerance_%=20, Value1="0.009 ohm", Value2=6.3V, ValueDisplayed=22µF
D1: "Diode, Zener, 18 V, 550 mW, SMB", Manufacturer="ON Semiconductor", Power_W=0.55, Supplier Part Number 1=45J2455, Value1=0.55W
D2: "LED, Blue, SMD", Color=Blue, Manufacturer="Wurth Elektronik", Power_TotalModule=0.105, Supplier Part Number 1=732-4966-1-ND, Value1=0.105W, Value2=3.2V
D3: "LED, Red, SMD", Color=Red, Manufacturer="Wurth Elektronik", Power_TotalModule=0.072, Supplier Part Number 1=732-4978-1-ND, Value1=0.072W, Value2=2V
FID1 FID2 FID3 FID4 FID5 FID6: "Fiducial mark.  There is nothing to buy or mount.", Manufacturer=N/A
J1: library part BoosterPack_40pin_J1J3, "Receptacle, 2.54mm, 10x2, Tin, TH", Alternate Manufacturer="Major League Electronics", Alternate PartNumber=CRD-081413-A-G, Manufacturer=Samtec, Supplier Part Number 1=SAM1204-10-ND
J2: library part BoosterPack_40pin_J2J4, "Receptacle, 2.54mm, 10x2, Tin, TH", Alternate Manufacturer="Major League Electronics", Alternate PartNumber=CRD-081413-A-G, Manufacturer=Samtec, Supplier Part Number 1=SAM1204-10-ND
J3: "Header, 2.54mm, 2x1, TH", Color=Black, Current_A=2, Manufacturer=3M, Supplier Part Number 1=3M9447-ND, Voltage_V=1000
J4: "Terminal Block, 3.5 mm, 2x1, Tin, TH", Manufacturer=Molex, Supplier Part Number 1=WM7877-ND
L1: "Inductor, Shielded Drum Core, Ferrite, 10 µH, 1.25 A, 0.18 ohm, SMD", Manufacturer=Coilcraft, Supplier Part Number 1=994-LPS4018-103MRB, Value1="0.18 ohm", Value2=1.25A, ValueDisplayed=10µH
L2: "Inductor, Drum Core, Ferrite, 330 µH, 0.18 A, 3.8 ohm, SMD", Manufacturer=Coilcraft, Value1="3.8 ohm", Value2=0.18A, ValueDisplayed=330µH
L3: "Inductor, Drum Core, Ferrite, 470 µH, 0.16 A, 5.06 ohm, SMD", Manufacturer=Coilcraft, Value1="5.06 ohm", Value2=0.16A, ValueDisplayed=470µH
L4: "Inductor, Wirewound, Ferrite, 1 µH, 0.595 A, 0.25 ohm, SMD", Manufacturer=MuRata, Value1="0.25 ohm", Value2=0.595A, ValueDisplayed=1µH
LBL1: library part THT-14-423-10, "Thermal Transfer Printable Labels, 0.650\" W x 0.200\" H - 10,000 per roll", Manufacturer=Brady, Supplier Part Number 1=97C5133
Logo1: library part Pb-Free
Logo2: library part FCC_disclaimer, "FCC_disclaimer"
Logo3: library part TI_Logo, "Texas Instrument Corporate Signature"
R1 R7 R10 R11 R20 R21 R24 R25: "RES, 0, 5%, 0.1 W, 0603", Manufacturer=Vishay-Dale, Power_W=0.1, Supplier Part Number 1=541-0.0GCT-ND, TempCo="200 ppm/C", Tolerance_%=5, Value1=5%, Value2=0.1W, Value_Code=0000, ValueDisplayed=0
R2 R8: "RES, 43 k, 5%, 0.1 W, 0603", Manufacturer=Vishay-Dale, Power_W=0.1, Supplier Part Number 1=541-43KGCT-ND, TempCo="200 ppm/C", Tolerance_%=5, Value1=5%, Value2=0.1W, Value_Code=43k0, ValueDisplayed=43k
R3 R4 R5 R6 R13 R14 R17: "RES, 10.0 k, 1%, 0.063 W, 0402", Manufacturer=Vishay-Dale, Power_W=0.063, Supplier Part Number 1=541-10.0KLCT-ND, TempCo="100 ppm/C", Tolerance_%=1, Value1=1%, Value2=0.063W, Value_Code=10k0, ValueDisplayed=10.0k
R9 R12: "RES, 510, 5%, 0.1 W, 0603", Manufacturer="Yageo America", Power_W=0.1, Supplier Part Number 1=311-510GRCT-ND, TempCo="100 ppm/C", Tolerance_%=5, Value1=5%, Value2=0.1W, Value_Code=510R, ValueDisplayed=510
R15: "RES, 33 k, 5%, 0.063 W, 0402", Manufacturer=Vishay-Dale, Power_W=0.063, Supplier Part Number 1=541-33KJCT-ND, TempCo="200 ppm/C", Tolerance_%=5, Value1=5%, Value2=0.063W, Value_Code=33k0, ValueDisplayed=33k
R16: "RES, 330, 5%, 0.063 W, 0402", Manufacturer=Vishay-Dale, Power_W=0.063, Supplier Part Number 1=541-330JCT-ND, TempCo="200 ppm/C", Tolerance_%=5, Value1=5%, Value2=0.063W, Value_Code=330R, ValueDisplayed=330
R18 R19: "RES, 680, 5%, 0.1 W, 0603", Manufacturer=Vishay-Dale, Power_W=0.1, Supplier Part Number 1=541-680GCT-ND, TempCo="200 ppm/C", Tolerance_%=5, Value1=5%, Value2=0.1W, Value_Code=680R, ValueDisplayed=680
R22 R23: "RES, 150, 1%, 0.1 W, 0603", Manufacturer=Vishay-Dale, Power_W=0.1, Supplier Part Number 1=541-150HCT-ND, TempCo="100 ppm/C", Tolerance_%=1, Value1=1%, Value2=0.1W, Value_Code=150R, ValueDisplayed=150
R26: "RES, 4.7, 5%, 0.125 W, 0805", Manufacturer=Panasonic, Power_W=0.125, Supplier Part Number 1=P4.7ACT-ND, TempCo="600 ppm/C", Tolerance_%=5, Value1=5%, Value2=0.125W, Value_Code=4R70, ValueDisplayed=4.7
R27 R28: "RES, 100 k, 1%, 0.1 W, 0603", Manufacturer="Yageo America", Power_W=0.1, Supplier Part Number 1=311-100KHRCT-ND, TempCo="200 ppm/C", Tolerance_%=1, Value1=1%, Value2=0.1W, Value_Code=100k
Rpg1: "RES, 100, 1%, 0.1 W, 0402", Manufacturer=Panasonic, Power_W=0.1, Supplier Part Number 1=P100LCT-ND, TempCo="100 ppm/C", Tolerance_%=1, Value1=1%, Value2=0.1W, Value_Code=100R, ValueDisplayed=100
U1: "Powerline Communications Analog Front End, 7 to 26 V, -40 to 125 degC, 48-pin QFN (RGZ0048B), Green (RoHS & no Sb/Br)", Alternate Manufacturer="Texas Instruments", Alternate PartNumber=Equivalent, Rating=Catalog, Supplier Part Number 1=296-29692-2-ND, Total Supply Voltage(Max)(+5V is 5, +/-5V is 10)=26, Total Supply Voltage(Min)(+5V is 5, +/-5V is 10)=7
U2: "28V, 0.5A Step-Down Converter with SNOOZE Mode, DQC0010A (WSON-10)", Alternate Manufacturer="Texas Instruments", Alternate PartNumber=TPS62177DQCT
U3: "Dual Buffer/Driver with Open-Drain Output, DBV0006A (SOT-6)", Alternate Manufacturer="Texas Instruments"
U4 U5 U6 U7 U8 U9: "Diode, Schottky, 50 V, 3 A, SMA", Manufacturer="Diodes Inc.", Supplier Part Number 1=B350A-FDICT-ND, Value1=3A, Value2=0.7V
ZZ1: library part AssemblyNoteLabel
ZZ2 ZZ3 ZZ4: library part AssemblyNote

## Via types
v1: diameter 26, hole 10, Top Layer to Bottom Layer, tented both sides, 66 vias
v2: diameter 20, hole 10, Top Layer to Bottom Layer, tented bottom, 12 vias
v3: diameter 22, hole 10, Top Layer to Bottom Layer, 3 vias

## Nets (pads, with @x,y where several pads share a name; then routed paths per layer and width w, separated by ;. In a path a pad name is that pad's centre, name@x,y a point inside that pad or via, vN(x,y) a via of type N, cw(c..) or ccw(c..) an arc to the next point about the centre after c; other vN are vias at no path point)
3V3: C17.1 C18.1 C19.1 C20.1 C21.1 C22.2 Cout1.1 J1.1 L1.2 R3.2 R4.2 R5.2 R6.2 R15.1 R18.2 R19.2 Rpg1.1 U1.2 U1.11 U1.30 U2.8 U2.10 U3.5 U4.1 | length 2142
  Top Layer w10: U4.1@684.26,608 705,587.26 v1(705,542) ; U1.11@964.42,1171.86 964.42,1186.07 970.87,1192.53 970.87,1239.13 v1(965,1245) 958,1252 958,1341 979,1362 C20.1@979,1391.5 ; U1.30@1043.16,904.14 1043.16,877.84 v1(1050,871) ; C19.1@1111,1389.5 1167,1333.5 1167,1302.05 1177.87,1291.18 1177.87,1259.7 1170.75,1252.57 1170.75,1227.71 1169.87,1226.83 1169.87,1206.87 1168.96,1205.96 1168.91,1206 v1(1167,1206) 1163.43,1206 1141.58,1184.15 U1.2@1141.58,1171.86
  Bottom Layer w10: v1(302,1380) 352.62,1380 C18.1@364,1391.38 ; C17.1@442.5,101 442.5,171.5 v1(481,210) 514.5,243.5 R18.2@738,243.5 R19.2@821,243.5 870.5,194 U3.5@961.87,194 ; R3.2@658.62,610 716,610 716,553 v1(705,542) ; 717,611 769.5,663.5 C21.1@832,663.5 ; C22.2@867.5,1730 v1(917,1730) ; v1(1060,1564) 1065,1559 1065,1549 ; v1(1504,569) 1515,558 R6.2@1596.38,558 ; v1@1536,842.38 R4.2@1591.38,787 ; v1(1540.5,1104) 1557.5,1087 R15.1@1587.38,1087 ; v1(1546,626) 1551,626 1552,625 1553,626 R5.2@1597.38,626 ; v1(1560,1560) 1560,1536.38 Rpg1.1@1587.38,1509
  Bottom Layer w11: 1588.38,1547.38 1634.2,1593.2 U2.8@1679.6,1593.2
  Bottom Layer w12: Rpg1.1@1588.38,1510 1588.38,1547.38
  other v1: 1048,440 463,483 1019,575 1536,845 1013,1579 1400,1816 1448,1882 1629,1891
ADCINA1: J1.29 R16.2 | length 798.1
  Top Layer w12: J1.29@350,300 413,363 413,653.62 700.38,941 R16.2@700.38,953
DAC_EN: J2.38 R13.2 U1.7 | length 1226.8
  Top Layer w8: U1.7@1043.16,1182.73 1037.25,1188.64 1037.25,1229.69 1037.13,1229.81 1037.13,1248.06 1037.25,1248.19 1037.25,1262.7 1068,1293.44 v1(1068,1319)
  Bottom Layer w12: v1(1068,1319) 1172,1319 1174,1321 1226.38,1268.62 1257.18,1268.62 1295.62,1230.18 1295.62,1225.18 1328.62,1192.18 1328.62,1166.38 1332,1163 1384,1163 1523,1024 1602.62,1024 R13.2@1636.62,990 1860,990 J2.38@1950,900
GND: C1.2 C3.2 C5.2 C6.2 C7.2 C8.2 C9.2 C10.2 C11.2 C12.2 C13.2 C14.2 C15.1 C16.2 C17.2 C18.2 C19.2 C20.2 C21.2 C22.1 C25.2 C26.2 Cin1.2 Cout1.2 D1.2 J1.22 J2.20 J3.1 J4.1 L3.2 R10.1 R13.1 R14.1 R17.1 R23.1 R28.1 U1.1 U1.12 U1.29 U1.34 U1.35 U1.38 U1.39 U1.40 U1.41 U1.49 U2.1 U2.4 U2.5 U2.6 U2.11@1717,1593.2 U3.2 U5.2 U8.2 U9.2 | length 2429.7
  Top Layer w10: v1(294,1557) 305,1568 ; v1(940,1206) 944.73,1210.73 v1@944.73,1198.73
  Top Layer w12: 305,1568 C3.2@383.26,1568 ; v1@358,1724 C1.2@456.26,1724 ; 615,1321 R10.1@704.5,1321 ; 758,163 C25.2@808.5,163 ; 761,101 R23.1@809.5,101 ; U1.12@944.73,1171.86 v1@944.73,1198.73 ; U1.1@1161.27,1171.86 1185.86,1171.86 v1(1203,1201) ; R17.1@1214,1287.62 1201,1465 v1(1232,1496) ; v1(1396,1548) 1445,1499 C16.2@1510,1499
  Bottom Layer w10: v1(294,1557) 294,1508.62 C18.2@364,1438.62 ; C17.2@505.5,101 732,101 v1(738,95) ; C21.2@832,726.5 832,736 v1(876,780) ; C22.1@866,1668.5 1059.5,1668.5 v1(1232,1496) ; v1(1229,954) 1229,959 1249.5,979.5 C14.2@1276,979.5 1352,979.5 1353.5,978 1386,978 1420.12,943.88 C12.2@1420.12,856 ; 1396,1534 1404.38,1525.62 C11.2@1447,1525.62 ; C15.1@1492,1113.5 1511,1113.5 v1(1540.5,1143) ; v3(1717,1593.2) U2.11@1717,1617
  Bottom Layer w12: v1(1012,100) 1012,179 1027,194 U3.2@1070.13,194 ; v1(1534,972) 1557.38,972 1564.38,965 ; R14.1@1589.38,936 1589.38,940 1564.38,965 ; R13.1@1589.38,990 1564.38,965
  other v1: 595,419 630,776 641,1045 1714,1189 604,1310 1803,1699 356,1726 1970,1811 2080,1886 1856,1896
  other v2: 1025.44,971.07 1079.57,972.06 1119.93,1010.44 988.04,1011.43 1026.29,1011.29 1079.71,1011.29 987.06,1064.57 1026.29,1064.71 1079.71,1064.71 1118.94,1064.57 1026.43,1103.94 1079.57,1103.94
  other v3: 1717,1558.2 1717,1628.2
INT_EN: J2.18 R15.2 U1.9 | length 1490.1
  Top Layer w8: v1(993,1290) 993,1202 992,1201 1003.79,1189.21 U1.9@1003.79,1171.86
  Bottom Layer w12: v1(993,1290) 993,1308 992,1309 1037,1354 1187,1354 1252.5,1288.5 1265.41,1288.5 1315.5,1238.41 1315.5,1233.41 1322.91,1226 1372.13,1226 1372.13,1250.1 1394.9,1272.87 1427.1,1272.87 1449.87,1250.1 1449.87,1226 1517,1226 1634.62,1108.38 R15.2@1634.62,1087 1711.75,1009.87 1868.23,1009.87 1922.49,955.61 1994.39,955.61 J2.18@2050,900
LED1_EN: J2.35 U3.1 | length 1776.8
  Bottom Layer w10: U3.1@1070.13,231.4 1200.73,362 1630,362 1862,130 2071,130 2121,180 2121,538 2102,557 2068.36,557 2067.97,556.61 2032.03,556.61 1988.64,600 J2.35@1950,600
LED2_EN: J2.36 U3.3 | length 1821.4
  Bottom Layer w10: U3.3@1070.13,156.6 1143.73,83 2057,83 2160,186 2160,588 2091.39,656.61 2032.03,656.61 1988.64,700 J2.36@1950,700
NetC2_1: C2.1 C3.1 R11.1 R12.1 | length 806.1
  Top Layer w12: C2.1@705.76,1134.74 R11.1@705.76,1191.26
  Top Layer w29: R12.1@704.5,1522 586.74,1522 C3.1@540.74,1568 540.74,1486.74 483,1429 483,1288 579.74,1191.26 R11.1@705.76,1191.26
NetC2_2: C2.2 U1.18 | length 182.7
  Top Layer w12: C2.2@771.5,1132 810.13,1093.37 820.96,1093.37 866.87,1047.46 U1.18@919.14,1047.46
NetC4_1: C4.1 U1.22 | length 199.7
  Top Layer w10: 860.46,967.97 U1.22@918.14,967.97
  Top Layer w12: C4.1@778,875 767.5,875 860.46,967.97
